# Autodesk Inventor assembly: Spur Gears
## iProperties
Created: 2008-01
Part Number: Spur Gears
Document SubType Name: Assembly
Designer: eruiz-tagle
Mass: 4.25267 g
Surface Area: 7.20162 cm^2
Volume: 0.541741 cm^3
Density: 7.85 g/cm^3
ClientObjectVersion: 1
Author: eruiz-tagle
